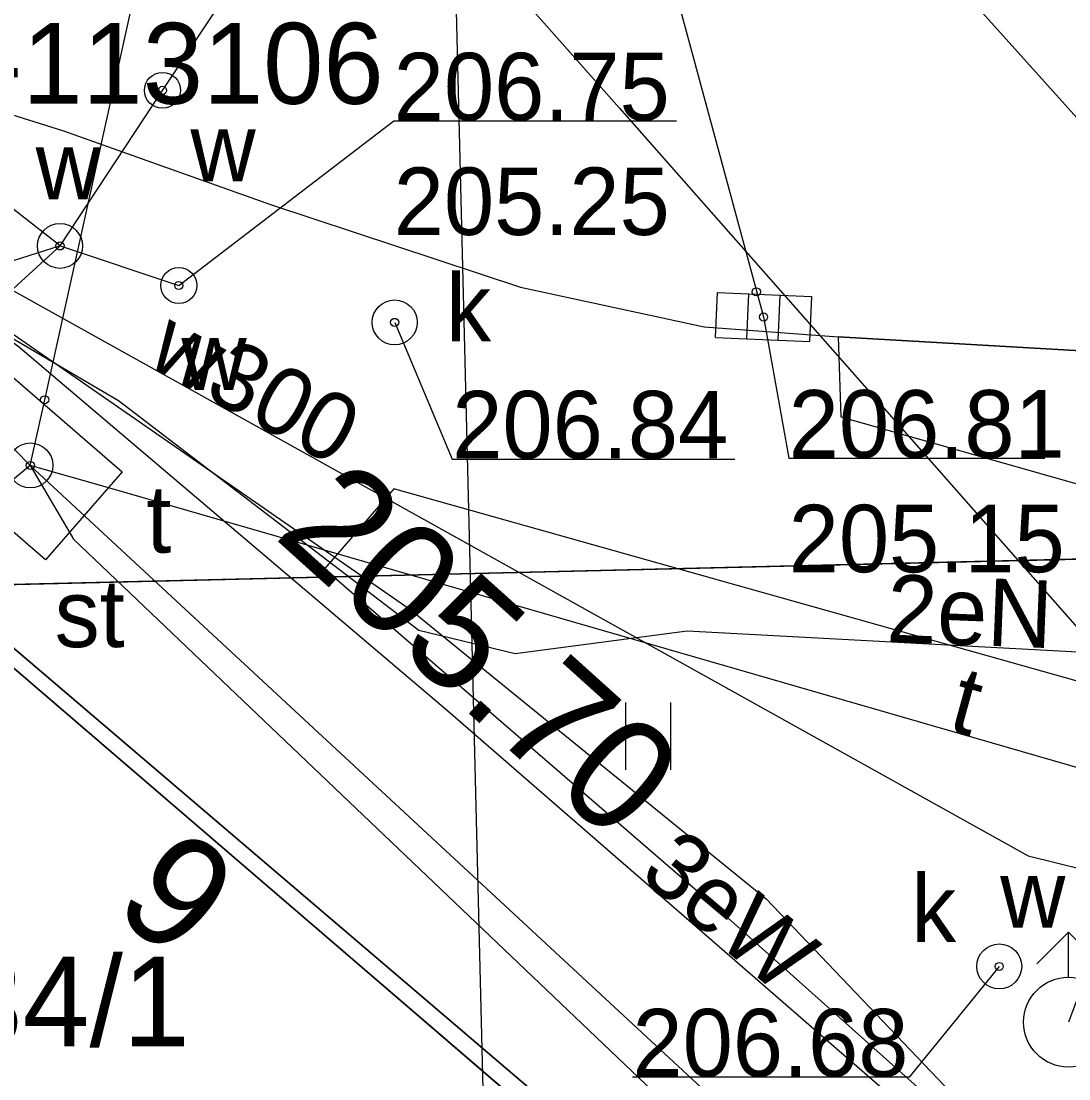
# Model space of a CAD drawing. Extents: x 6512400 to 6513200, y 6022500 to 6022750.
# Drawn here: x 6512803.1 to 6512814.74, y 6022664.87 to 6022676.63 of the extents above; entities that cross this region are included whole.
import ezdxf

# ---------------------------------------------------------------- set-up
doc = ezdxf.new("R2010")
doc.units = 0
for name, color, linetype in [('121-Punkt osnowy szczegółowej-Atr103', 7, 'Continuous'), ('211-numer działki ewidencyjnej', 7, 'Continuous'), ('216-obręb ewidencyjny', 7, 'Continuous'), ('217-kontur klasyfikacyjny', 7, 'Continuous'), ('218-kontur użytku gruntowego', 7, 'Continuous'), ('219-działka ewidencyjna', 7, 'Continuous'), ('238-Punkt adresowy budynku', 7, 'Continuous'), ('312-budynek ewidencyjny', 7, 'Continuous'), ('940-Trawnik symb. poj.', 7, 'Continuous'), ('chodnik (powierzchnia)', 7, 'Continuous'), ('hydrant (punkt)', 7, 'Continuous'), ('inna obudowa przewodu - sieć telekomunikacyjna (linia)', 7, 'Continuous'), ('komora podziemna - przewód telekomunikacyjny (powierzchnia)', 7, 'Continuous'), ('kratka ściekowa (punkt)', 7, 'Continuous'), ('krawężnik (linia)', 7, 'Continuous'), ('Obszar opracowania', 7, 'Continuous'), ('przewód elektroenergetyczny (linia)', 7, 'Continuous'), ('przewód elektroenergetyczny (linia)-Atr1', 7, 'Continuous'), ('przewód kanalizacyjny (linia)', 7, 'Continuous'), ('przewód telekomunikacyjny (linia)', 7, 'Continuous'), ('przewód telekomunikacyjny (linia)-Atr1', 7, 'Continuous'), ('przewód wodociągowy (linia)', 7, 'Continuous'), ('przewód wodociągowy (linia)-Atr1', 7, 'Continuous'), ('punkt o określonej wysokości (sieć kanalizacyjna)', 7, 'Continuous'), ('punkt o określonej wysokości (sieć kanalizacyjna)-Atr2', 7, 'Continuous'), ('punkt o określonej wysokości (sieć kanalizacyjna)-Atr3', 7, 'Continuous'), ('punkt o określonej wysokości (sieć telekomunikacyjna)', 7, 'Continuous'), ('punkt o określonej wysokości (sieć telekomunikacyjna)-Atr2', 7, 'Continuous'), ('punkt o określonej wysokości (sieć wodociągowa)', 7, 'Continuous'), ('punkt o określonej wysokości (sieć wodociągowa)-Atr2', 7, 'Continuous'), ('punkt o określonej wysokości (sieć wodociągowa)-Atr3', 7, 'Continuous'), ('szafa telekomunikacyjna (punkt)-Atr17', 7, 'Continuous'), ('właz okrągły - siec kanalizacyjna (punkt)', 7, 'Continuous'), ('właz okrągły - siec kanalizacyjna (punkt)-Atr17', 7, 'Continuous'), ('właz okrągły - siec telekomunikacyjna (punkt)', 7, 'Continuous'), ('właz okrągły - siec telekomunikacyjna (punkt)-Atr17', 7, 'Continuous'), ('właz okrągły - siec wodociągowa (punkt)', 7, 'Continuous'), ('właz okrągły - siec wodociągowa (punkt)-Atr17', 7, 'Continuous'), ('zasuwa - siec wodociągowa (punkt)', 7, 'Continuous'), ('zasuwa - siec wodociągowa (punkt)-Atr17', 7, 'Continuous')]:
    doc.layers.add(name, color=color, linetype=linetype)

# ---------------------------------------------------------------- blocks, each defined once
blk = doc.blocks.new('PW01')
blk.add_circle((0, 0), 0.045)
blk = doc.blocks.new('US05')
for p, q in [((-0.525, -0.25), (-0.525, 0.25)), ((-0.525, 0.25), (-0.175, 0.25)), ((-0.175, -0.25), (-0.175, 0.25)), ((-0.175, 0.25), (0.175, 0.25)), ((0.175, -0.25), (0.175, 0.25)), ((0.175, 0.25), (0.525, 0.25)), ((0.525, -0.25), (0.525, 0.25)), ((-0.525, -0.25), (-0.175, -0.25)), ((-0.175, -0.25), (0.175, -0.25)), ((0.175, -0.25), (0.525, -0.25))]:
    blk.add_line(p, q)
blk = doc.blocks.new('US22')
blk.add_circle((0, 0), 0.25)
blk = doc.blocks.new('US02')
for p, q in [((0, 1), (-0.353, 0.647)), ((0, 0.5), (0, 1)), ((0, 1), (0.354, 0.647))]:
    blk.add_line(p, q)
blk.add_circle((0, 0), 0.5)
blk = doc.blocks.new('940P')
for p, q in [((-0.25, -0.375), (-0.25, 0.375)), ((0.25, -0.375), (0.25, 0.375))]:
    blk.add_line(p, q)
blk = doc.blocks.new('US25')
blk.add_circle((0, 0), 0.2)

msp = doc.modelspace()

# ---------------------------------------------------------------- linework, layer by layer
at = {"layer": '216-obręb ewidencyjny'}
for points in [[(6512688.62, 6022674.91), (6512702.58, 6022674.18), (6512725.78, 6022672.95), (6512730.35, 6022672.71), (6512735.76, 6022672.94), (6512745.51, 6022673.33), (6512754.87, 6022673.72), (6512768.24, 6022674.27), (6512785.56, 6022674.74), (6512790.49, 6022674.74), (6512796.96, 6022674.74), (6512801.96, 6022670.34), (6512828.67, 6022670.98), (6512833.61, 6022675.02), (6512836.69, 6022675.17), (6512851.94, 6022675.93)], [(6512836.687, 6022675.173), (6512833.61, 6022675.02), (6512828.67, 6022670.98), (6512801.96, 6022670.34), (6512810.18, 6022663.28), (6512825.37, 6022649.66), (6512838.47, 6022634.29), (6512852.25, 6022608.25), (6512853.17, 6022604.51), (6512855.78, 6022583.95), (6512858.85, 6022571.74), (6512828.23, 6022562.62), (6512818.47, 6022559.72), (6512824.714, 6022553.406)], [(6512780.7, 6022581.02), (6512806.2, 6022572.11), (6512806.62, 6022563.51), (6512811.41, 6022558.95), (6512818.47, 6022559.72), (6512828.23, 6022562.62), (6512858.85, 6022571.74), (6512855.78, 6022583.95), (6512853.17, 6022604.51), (6512852.25, 6022608.25), (6512838.47, 6022634.29), (6512825.37, 6022649.66), (6512810.18, 6022663.28), (6512801.96, 6022670.34), (6512796.96, 6022674.74), (6512790.49, 6022674.74), (6512785.56, 6022674.74), (6512768.24, 6022674.27)]]:
    msp.add_lwpolyline(points, dxfattribs=at)
at = {"layer": '217-kontur klasyfikacyjny'}
msp.add_lwpolyline([(6512810.18, 6022663.28), (6512801.96, 6022670.34)], dxfattribs=at)
at = {"layer": '218-kontur użytku gruntowego'}
for points in [[(6512801.96, 6022670.34), (6512828.67, 6022670.98)], [(6512828.67, 6022670.98), (6512801.96, 6022670.34)], [(6512810.18, 6022663.28), (6512801.96, 6022670.34)], [(6512801.96, 6022670.34), (6512810.18, 6022663.28)]]:
    msp.add_lwpolyline(points, dxfattribs=at)
at = {"layer": '219-działka ewidencyjna'}
for points in [[(6512828.67, 6022670.98), (6512801.96, 6022670.34)], [(6512801.96, 6022670.34), (6512810.18, 6022663.28)]]:
    msp.add_lwpolyline(points, dxfattribs=at)
at = {"layer": '312-budynek ewidencyjny'}
msp.add_lwpolyline([(6512802.06, 6022670.47), (6512810.3, 6022663.44)], dxfattribs=at)
at = {"layer": 'chodnik (powierzchnia)'}
for points in [[(6512845.61, 6022610.5), (6512844.69, 6022613.44), (6512844.06, 6022613.28), (6512843.41, 6022615.01), (6512844.01, 6022615.23), (6512838.87, 6022629.83), (6512839.52, 6022630.32), (6512838.94, 6022631.84), (6512838.15, 6022631.88), (6512837.86, 6022632.79), (6512838.13, 6022633.96), (6512826.89, 6022646.81), (6512825.11, 6022648.85), (6512824.32, 6022649.76), (6512820.29, 6022654.03), (6512817.62, 6022656.88), (6512816.1, 6022658.5), (6512810.3, 6022663.44), (6512802.06, 6022670.47), (6512797.05, 6022674.74)], [(6512830.64, 6022661.41), (6512827.95, 6022665.6), (6512807.24, 6022671.43), (6512806.47, 6022670.54), (6512810.75, 6022666.84), (6512818.47, 6022659.95)]]:
    msp.add_lwpolyline(points, dxfattribs=at)
msp.add_lwpolyline([(6512812.21, 6022672.23), (6512829.02, 6022667.46), (6512831.23, 6022666.85), (6512832.78, 6022666.53), (6512833.94, 6022666.42), (6512838.17, 6022666.38), (6512837.9, 6022666.78), (6512836.24, 6022668.51), (6512834.25, 6022670.06), (6512832.02, 6022671.17), (6512829.48, 6022671.98), (6512827.66, 6022672.22), (6512821.17, 6022672.6), (6512812.18, 6022673.12)], close=True, dxfattribs=at)
at = {"layer": 'inna obudowa przewodu - sieć telekomunikacyjna (linia)'}
for points in [[(6512803.35, 6022672.37), (6512803.36, 6022672.42), (6512806.94, 6022688.62), (6512806.95, 6022688.66)], [(6512829.04, 6022664.23), (6512828.99, 6022664.24), (6512804.11, 6022671.43), (6512804.07, 6022671.44)]]:
    msp.add_lwpolyline(points, dxfattribs=at)
at = {"layer": 'komora podziemna - przewód telekomunikacyjny (powierzchnia)'}
msp.add_lwpolyline([(6512804.22, 6022671.62), (6512803.37, 6022670.64), (6512802.05, 6022671.78), (6512802.89, 6022672.77)], close=True, dxfattribs=at)
at = {"layer": 'krawężnik (linia)'}
msp.add_lwpolyline([(6512799.61, 6022676.46), (6512800.1, 6022676.4), (6512801.75, 6022675.98), (6512803.57, 6022675.41), (6512805.87, 6022674.59), (6512808.65, 6022673.67), (6512810.69, 6022673.23), (6512812.18, 6022673.12), (6512821.17, 6022672.6), (6512827.66, 6022672.22)], dxfattribs=at)
at = {"layer": 'Obszar opracowania'}
msp.add_lwpolyline([(6512710.98, 6022693.84), (6512748.35, 6022694.16), (6512798.11, 6022695.25), (6512807.47, 6022695.46), (6512809.66, 6022606.87), (6512863.71, 6022622.03), (6512875.13, 6022581.36), (6512755.22, 6022535.25), (6512691.61, 6022568.03), (6512709.16, 6022605.16)], close=True, dxfattribs=at)
at = {"layer": 'przewód elektroenergetyczny (linia)'}
for points in [[(6512763.38, 6022676.06), (6512798.79, 6022676.04), (6512803.06, 6022673.02), (6512807.84, 6022668.96), (6512815.24, 6022662.53), (6512819.98, 6022657.77), (6512831.6, 6022645.79), (6512834.59, 6022642.25), (6512837.06, 6022638.75), (6512840.02, 6022634.13), (6512842.26, 6022630.04), (6512846.03, 6022621.35), (6512846.58, 6022618.9), (6512847.6, 6022616.23), (6512852.12, 6022605.09), (6512853.39, 6022601.13), (6512855.57, 6022592.48), (6512858.1, 6022582.86), (6512868.09, 6022584.49), (6512870.03, 6022584.23), (6512871.36, 6022584.34), (6512875.65, 6022585.56), (6512879.74, 6022586.61), (6512881.754, 6022587.357)], [(6512776, 6022676.02), (6512799.41, 6022675.19), (6512801.88, 6022673.76), (6512804.18, 6022672.41), (6512807.52, 6022669.86), (6512808.59, 6022669.6), (6512810.5, 6022669.85), (6512831.73, 6022668.71)], [(6512802.27, 6022673.66), (6512807.42, 6022670.09), (6512811.38, 6022666.87), (6512814.66, 6022663.43), (6512826.4, 6022651.65), (6512827.82, 6022650.09), (6512834.03, 6022642.46), (6512842.84, 6022631.19), (6512844.67, 6022626.95), (6512847.57, 6022619.87), (6512849.81, 6022612.67), (6512853.56, 6022600.08), (6512856.46, 6022588.83), (6512861.26, 6022569.82), (6512861.768, 6022567.654)]]:
    msp.add_lwpolyline(points, dxfattribs=at)
at = {"layer": 'przewód kanalizacyjny (linia)'}
for points in [[(6512808.18, 6022685.05), (6512811.35, 6022673.34)], [(6512803.88, 6022681.97), (6512807.28, 6022678.45), (6512809.75, 6022675.66)], [(6512809.75, 6022675.66), (6512823.01, 6022660.61), (6512831.4, 6022651.41), (6512840.81, 6022640.51)]]:
    msp.add_lwpolyline(points, dxfattribs=at)
at = {"layer": 'przewód telekomunikacyjny (linia)'}
for points in [[(6512803.2, 6022671.69), (6512803.36, 6022672.42), (6512806.94, 6022688.62), (6512807.08, 6022689.26)], [(6512803.2, 6022671.69), (6512802.51, 6022672.39), (6512787.26, 6022687.76), (6512786.53, 6022688.5)], [(6512829.92, 6022664.12), (6512829.04, 6022664.23), (6512828.99, 6022664.24), (6512804.11, 6022671.43), (6512803.2, 6022671.69)], [(6512803.2, 6022671.69), (6512803.68, 6022670.87), (6512814.12, 6022660.92), (6512820.62, 6022654.75), (6512822.04, 6022653.36), (6512827.37, 6022648.58), (6512829.25, 6022646.9)], [(6512829.25, 6022646.9), (6512828.69, 6022647.83), (6512819.07, 6022656.76), (6512812.33, 6022663.22), (6512803.2, 6022671.69)]]:
    msp.add_lwpolyline(points, dxfattribs=at)
at = {"layer": 'przewód wodociągowy (linia)'}
for points in [[(6512809.35, 6022681.88), (6512813.75, 6022676.76), (6512817.99, 6022672.04), (6512824.14, 6022665.03), (6512827.96, 6022660.57), (6512832.92, 6022654.39), (6512839.85, 6022645.35)], [(6512776.98, 6022676.45), (6512777.41, 6022676.47), (6512777.83, 6022676.47), (6512787.32, 6022676), (6512787.61, 6022675.99), (6512796.6, 6022675.55), (6512799.85, 6022675.39), (6512814.29, 6022667.35), (6512815.22, 6022667.12), (6512815.2, 6022666.73), (6512814.74, 6022665.5)], [(6512803.53, 6022674.13), (6512802.06, 6022675.28), (6512802.33, 6022676.21)], [(6512803.53, 6022674.13), (6512804.67, 6022675.86)], [(6512803.53, 6022674.13), (6512800.75, 6022671.59)], [(6512803.53, 6022674.13), (6512804.85, 6022673.69)]]:
    msp.add_lwpolyline(points, dxfattribs=at)
at = {"layer": 'punkt o określonej wysokości (sieć kanalizacyjna)-Atr2'}
for points in [[(6512807.25, 6022673.28), (6512807.89, 6022671.76), (6512811.031, 6022671.76)], [(6512811.35, 6022673.34), (6512811.63, 6022671.77), (6512814.478, 6022671.77)], [(6512813.97, 6022666.12), (6512812.97, 6022664.89), (6512809.893, 6022664.89)]]:
    msp.add_lwpolyline(points, dxfattribs=at)
at = {"layer": 'punkt o określonej wysokości (sieć telekomunikacyjna)-Atr2'}
msp.add_lwpolyline([(6512803.2, 6022671.69), (6512800.87, 6022669.76), (6512797.729, 6022669.76)], dxfattribs=at)
at = {"layer": 'punkt o określonej wysokości (sieć wodociągowa)-Atr2'}
for points in [[(6512804.67, 6022675.86), (6512806.21, 6022678.18), (6512809.287, 6022678.18)], [(6512804.85, 6022673.69), (6512807.24, 6022675.52), (6512810.381, 6022675.52)], [(6512803.53, 6022674.13), (6512798.79, 6022672.62), (6512795.617, 6022672.62)]]:
    msp.add_lwpolyline(points, dxfattribs=at)

# ---------------------------------------------------------------- block references
at = {"layer": '940-Trawnik symb. poj.'}
msp.add_blockref('940P', (6512810.07, 6022668.68), dxfattribs=at)
at = {"layer": 'hydrant (punkt)'}
msp.add_blockref('US02', (6512814.74, 6022665.5), dxfattribs=at)
at = {"layer": 'kratka ściekowa (punkt)', "rotation": -2.526}
msp.add_blockref('US05', (6512811.35, 6022673.34), dxfattribs=at)
at = {"layer": 'punkt o określonej wysokości (sieć kanalizacyjna)'}
for p, rotation in [((6512811.27, 6022673.62), -74.074), ((6512811.35, 6022673.34), -2.526)]:
    msp.add_blockref('PW01', p, dxfattribs=dict(at, rotation=rotation))
for p in [(6512807.25, 6022673.28), (6512813.97, 6022666.12)]:
    msp.add_blockref('PW01', p, dxfattribs=at)
at = {"layer": 'punkt o określonej wysokości (sieć telekomunikacyjna)'}
for p, rotation in [((6512803.36, 6022672.42), 78.328), ((6512803.2, 6022671.69), -43.02)]:
    msp.add_blockref('PW01', p, dxfattribs=dict(at, rotation=rotation))
at = {"layer": 'punkt o określonej wysokości (sieć wodociągowa)'}
for p, rotation in [((6512804.67, 6022675.86), 57.614), ((6512804.85, 6022673.69), -32.218)]:
    msp.add_blockref('PW01', p, dxfattribs=dict(at, rotation=rotation))
msp.add_blockref('PW01', (6512803.53, 6022674.13), dxfattribs=at)
at = {"layer": 'właz okrągły - siec kanalizacyjna (punkt)'}
for p in [(6512807.25, 6022673.28), (6512813.97, 6022666.12)]:
    msp.add_blockref('US22', p, dxfattribs=at)
at = {"layer": 'właz okrągły - siec telekomunikacyjna (punkt)', "rotation": -43.02}
msp.add_blockref('US22', (6512803.2, 6022671.69), dxfattribs=at)
at = {"layer": 'właz okrągły - siec wodociągowa (punkt)'}
msp.add_blockref('US22', (6512803.53, 6022674.13), dxfattribs=at)
at = {"layer": 'zasuwa - siec wodociągowa (punkt)'}
for p, rotation in [((6512804.67, 6022675.86), 57.614), ((6512804.85, 6022673.69), -32.218)]:
    msp.add_blockref('US25', p, dxfattribs=dict(at, rotation=rotation))

# ---------------------------------------------------------------- texts
at = {"layer": '121-Punkt osnowy szczegółowej-Atr103'}
msp.add_text('314.444-113106', height=0.9, dxfattribs=at).set_placement((6512798.36, 6022675.71))
at = {"layer": '211-numer działki ewidencyjnej'}
msp.add_text('34/1', height=1, dxfattribs=at).set_placement((6512802.37, 6022665.23))
at = {"layer": '238-Punkt adresowy budynku'}
msp.add_text('6', height=1.25, rotation=140.357, dxfattribs=at).set_placement((6512805.6, 6022667.12))
at = {"layer": 'przewód elektroenergetyczny (linia)-Atr1'}
for s, rotation, p in [('2eN', 357.735, (6512812.71, 6022669.73)), ('3eW', 319.843, (6512809.95, 6022667.12))]:
    msp.add_text(s, height=0.75, rotation=rotation, dxfattribs=at).set_placement(p)
at = {"layer": 'przewód telekomunikacyjny (linia)-Atr1'}
msp.add_text('t', height=0.75, rotation=344.685, dxfattribs=at).set_placement((6512813.38, 6022668.75))
at = {"layer": 'przewód wodociągowy (linia)-Atr1'}
msp.add_text('w300', height=0.75, rotation=331.683, dxfattribs=at).set_placement((6512804.47, 6022672.81))
at = {"layer": 'punkt o określonej wysokości (sieć kanalizacyjna)-Atr2'}
for s, p in [('206.84', (6512807.89, 6022671.768)), ('206.81', (6512811.63, 6022671.777)), ('206.68', (6512809.893, 6022664.897))]:
    msp.add_text(s, height=0.75, dxfattribs=at).set_placement(p)
at = {"layer": 'punkt o określonej wysokości (sieć kanalizacyjna)-Atr3'}
msp.add_text('205.15', height=0.75, dxfattribs=at).set_placement((6512811.63, 6022670.502))
at = {"layer": 'punkt o określonej wysokości (sieć telekomunikacyjna)'}
msp.add_text('205.70', height=1.25, rotation=317.962, dxfattribs=at).set_placement((6512805.89, 6022670.9))
at = {"layer": 'punkt o określonej wysokości (sieć wodociągowa)-Atr2'}
msp.add_text('206.75', height=0.75, dxfattribs=at).set_placement((6512807.24, 6022675.527))
at = {"layer": 'punkt o określonej wysokości (sieć wodociągowa)-Atr3'}
msp.add_text('205.25', height=0.75, dxfattribs=at).set_placement((6512807.24, 6022674.252))
at = {"layer": 'szafa telekomunikacyjna (punkt)-Atr17'}
msp.add_text('st', height=0.75, dxfattribs=at).set_placement((6512803.47, 6022669.67))
at = {"layer": 'właz okrągły - siec kanalizacyjna (punkt)-Atr17'}
for p in [(6512807.82, 6022673.07), (6512812.99, 6022666.39)]:
    msp.add_text('k', height=0.75, dxfattribs=at).set_placement(p)
at = {"layer": 'właz okrągły - siec telekomunikacyjna (punkt)-Atr17'}
msp.add_text('t', height=0.75, dxfattribs=at).set_placement((6512804.49, 6022670.72))
at = {"layer": 'właz okrągły - siec wodociągowa (punkt)-Atr17'}
msp.add_text('w', height=0.75, dxfattribs=at).set_placement((6512803.26, 6022674.65))
at = {"layer": 'zasuwa - siec wodociągowa (punkt)-Atr17'}
for p in [(6512804.98, 6022674.85), (6512804.88, 6022672.53), (6512813.98, 6022666.55)]:
    msp.add_text('w', height=0.75, dxfattribs=at).set_placement(p)

doc.saveas('drawing.dxf')
